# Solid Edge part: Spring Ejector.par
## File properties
Author: Dan
Template: Normal.par
Last saved by: Dan
Revision: 143
Application: Solid Edge
Density: 7.850 kg/dm^3
Accuracy: 0.99
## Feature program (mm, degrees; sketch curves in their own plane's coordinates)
helix protrusion "HelixProtrusion_1"
helix protrusion "HelixProtrusion_2"  NumberOfTurns = 1
helix protrusion "HelixProtrusion_3"  NumberOfTurns = 1
sketch for "unnamed Cutout 1" plane through (0, 0, 0) normal (0, -1, 0) x-axis (1, 0, 0)
  line (-62, 12.5) -> (-62, 6.5)
extrude "unnamed Cutout 1" cut through
sketch for "unnamed Cutout 2" plane through (0, 0, 0) normal (0, -1, 0) x-axis (1, 0, 0)
  line (58, 6.5) -> (58, 12.5)
extrude "unnamed Cutout 2" cut through
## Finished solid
Body 1: solid body, 8 faces, 18 edges, 12 vertices.
  Faces by surface: spline 4, cylinder 2, plane 2
  Edges by curve: spline 8, circle 4, line 4, intersection 2
Bounding box of the edges (mm; curved faces can reach further): 120.000 x 25.000 x 25.000, from (-62, -12.5, -12.5) to (58, 12.5, 12.5).
Cylindrical faces by radius (mm): R6.5 x1, R12.5 x1
Planar faces by outward normal: +x 1, -x 1
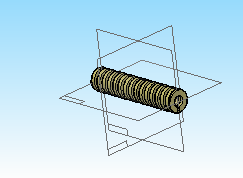
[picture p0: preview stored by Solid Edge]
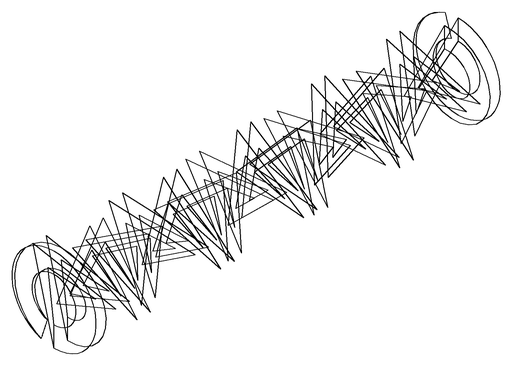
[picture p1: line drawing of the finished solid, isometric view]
